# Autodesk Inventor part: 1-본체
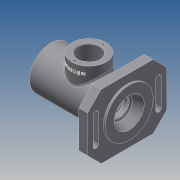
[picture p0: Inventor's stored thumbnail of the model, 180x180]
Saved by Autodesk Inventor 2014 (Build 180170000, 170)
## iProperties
Created: 2017-10
Part Number: 1-본체
Material: Generic
Document SubType Name: Modeling
Designer: kb543-11
Density: 1 g/cm^3
Appearance: Default
Author: kb543-11
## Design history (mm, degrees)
sketch "스케치1"
  geometry: L1 (-48.5, 0)-(-48.5, 24); L2 (-48.5, 24)-(-45.5, 24); L3 (-45.5, 24)-(-45.5, 20); L4 (-45.5, 20)-(-36.5, 20); L5 (-36.5, 20)-(-36.5, 17.5); L6 (-36.5, 17.5)-(-33.25, 17.5); L7 (-33.25, 17.5)-(-33.25, 18.5); L8 (-33.25, 18.5)-(-31.5, 18.5); L9 (-31.5, 18.5)-(-31.5, 17.5); L10 (-31.5, 17.5)-(-20.5, 17.5); L11 (-20.5, 17.5)-(-20.5, 26); L12 (-20.5, 26)-(17.5, 26); L13 (17.5, 26)-(17.5, 17.5); L14 (33.5, 16.5)-(33.5, 10); L15 (33.5, 10)-(36.2, 10); L16 (36.2, 10)-(36.2, 12.5); L17 (36.2, 12.5)-(42.8, 12.5); L18 (43.5, 16)-(57.5, 22); L19 (57.5, 22)-(57.5, 35); L20 (57.5, 0)-(-57.5, 0); L21 (43.5, 16)-(43.5, 12.904); L22 (42.8, 12.5)-(43.5, 12.904); L23 (17.5, 17.5)-(28.5, 17.5); L24 (28.5, 17.5)-(28.5, 16.5); L25 (28.5, 16.5)-(33.5, 16.5); L26 (-57.5, 31)-(-57.5, 0); L27 (57.5, 35)-(54.5, 35); L28 (-57.5, 31)-(54.5, 31); L29 (54.5, 31)-(54.5, 35); 2 further points
  constraints: 58 end point, 11 parallel, 5 perpendicular, 1 coincident, 1 midpoint, 1 point on line, 1 vertical, 1 vertical alignment
  dimensions: "d1" = 48 diameter of L2 L20; "d4" = 3 distance of L1.end L2.end; "d7" = 40 diameter of L4 L20; "d8" = 35 diameter of L6 L20; "d9" = 1.75 distance of L7.end L8.end; "d10" = 37 diameter of L8 L20; "d12" = 11 distance of L9.end L10.end; "d13" = 35 diameter of L10 L20; "d14" = 52 diameter of L12 L20; "d15" = 32 diameter of L18.start L20; "d16" = 44 diameter of L18.end L20; "d18" = 38 distance between parallel lines of L13 L11; "d19" = 14 distance between parallel lines of L19 L21; "d24" = 30 deg angle of L22 L17; "d25" = 0.7 horizontal distance of L21.end L17.end; "d26" = 7.3 distance between parallel lines of L16 L21; "d28" = 25 diameter of L17 L20; "d29" = 2.7 distance of L14.end L15.end; "d30" = 20 diameter of L15 L20; "d31" = 35 diameter of L23 L20; "d32" = 33 diameter of L25 L20; "d33" = 11 distance between parallel lines of L24 L13; "d90" = 12 distance between parallel lines of L3 L26; "d91" = 115 distance between parallel lines of L19 L26; "d92" = 21 distance between parallel lines of L26 L5; "d93" = 26 distance between parallel lines of L26 L9; "d101" = 62 diameter of L28 L20; "d102" = 3 distance of L19.end L27.end; "d103" = 70 diameter of L27 L20
revolve "회전1" sketch "스케치1" stored, may be unused: angle "d34" = 90 deg
sketch "스케치8"
  geometry: C1 r 31 at (0, 0) reference; 1 further point
  constraints: 1 coincident
hole "구멍2" sketch "스케치8" at (0, 0) diameter "d94" = 40.376; stored, may be unused: countersink angle "d98" = 90 deg, drill point angle "d100" = 118 deg; dims "d95" = 6, "d96" = 4, "d97" = 2, "d99" = 8
node "작업 평면1"
sketch "스케치2"
  geometry: L1 (-38, 47)-(38, 47); L2 (58, 27)-(58, -27); L3 (38, -47)-(-38, -47); L4 (-58, -27)-(-58, 27); L5 (-58, 47)-(58, -47); L6 (58, 47)-(-58, -47); L7 (-38, 47)-(-58, 27); L8 (-58, -27)-(-38, -47); L9 (38, -47)-(58, -27); L10 (58, 27)-(38, 47); C1 r 31 at (0, 0) reference; 1 further point
  constraints: 20 end point, 8 point on line, 2 midpoint, 2 parallel, 1 horizontal, 1 perpendicular
  dimensions: "d39" = 116 distance of L5.start L6.start; "d40" = 94 distance of L6.start L5.end; "d41" = 20 distance of L1.start L5.start; "d42" = 20 distance of L4.end L5.start (= d41); "d43" = 20 distance of L4.start L6.end (= d41); "d44" = 20 distance of L3.end L6.end (= d43); "d45" = 20 distance of L3.start L5.end (= d41); "d46" = 20 distance of L2.end L5.end (= d45); "d47" = 20 distance of L2.start L6.start; "d48" = 20 distance of L1.end L6.start (= d47)
extrude "돌출5" join sketch "스케치2" distance "d104" = 13; taper "d105" = 0 deg
sketch "스케치9"
  geometry: L1 (58, -27)-(58, 27) reference; L2 (46, -20)-(46, 20); L3 (42, -20)-(42, 20); L4 (50, 20)-(50, -20); L5 (-46, -20)-(-46, 20); L6 (-50, -20)-(-50, 20); L7 (-42, 20)-(-42, -20); C1 r 31 at (0, 0) reference; A1 r 4 centre (46, -20) between (42, -20) and (50, -20); A2 r 4 centre (46, 20) between (50, 20) and (42, 20); A3 r 4 centre (-46, -20) between (-50, -20) and (-42, -20); A4 r 4 centre (-46, 20) between (-42, 20) and (-50, 20); 2 further points
  constraints: 16 end point, 8 point on circle, 8 tangent, 4 centre point, 4 parallel, 3 horizontal alignment, 2 midpoint
  dimensions: "d106" = 46 distance from line of L2 C1.centre; "d107" = 92 distance between parallel lines of L5 L2; "d108" = 4 radius of A3; "d109" = 4 radius of A1; "d110" = 40 distance of L5.start L5.end
extrude "돌출6" cut sketch "스케치9" stored distance "d111" = 13; taper "d112" = 0 deg
node "작업 평면2"
sketch "스케치4"
  geometry: L1 (57.5, 31)-(57.5, -31) reference; C1 r 25 at (1.5, 0); 2 further points
  constraints: 1 centre point, 1 horizontal alignment, 1 midpoint
  dimensions: "d58" = 50 diameter of C1; "d59" = 56 distance from line of L1 C1.centre
extrude "돌출3" join sketch "스케치4" stored distance "d60" = 13; taper "d61" = 0 deg
sketch "스케치5"
  geometry: C1 r 25 at (0, 0) reference; C2 r 16 at (0, 0); 1 further point
  constraints: 1 centre point, 1 coincident
  dimensions: "d62" = 32 diameter of C2
extrude "돌출4" cut sketch "스케치5" stored distance "d63" = 13; taper "d64" = 0 deg
node "작업 평면3"
sketch "스케치6"
  geometry: L1 (-56, -78)-(-56, -16) reference; L2 (-25, 0)-(25, 0) reference; 2 further points
  constraints: 1 other
  dimensions: "d65" = 56 distance from line of L1 point (0, -10); "d66" = 10 distance from line of point (0, -10) L2
feature "엠보싱1" sketch "스케치6" dims "d1" = 48, "d4" = 3, "d7" = 40, "d8" = 35, "d9" = 1.75, "d10" = 37, "d12" = 11, "d13" = 35, "d14" = 52, "d15" = 32, "d16" = 44, "d18" = 38, "d19" = 14, "d24" = 30 deg, "d25" = 0.7, "d26" = 7.3, "d28" = 25, "d29" = 2.7, "d30" = 20, "d31" = 35, "d32" = 33, "d33" = 11, "d67" = 0.5, "d68" = 0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
sketch "스케치7"
  geometry: C1 r 16 at (0, 0) reference; 3 further points
  constraints: 2 vertical alignment
  dimensions: "d69" = 20.5 distance of C1.centre point (0, 20.5); "d70" = 41 distance of point (0, -20.5) point (0, 20.5)
hole "구멍1" sketch "스케치7" at (0, 20.5), (0, -20.5) diameter "d71" = 2.459; stored, may be unused: countersink angle "d75" = 90 deg, drill point angle "d77" = 118 deg; dims "d72" = 6, "d73" = 4, "d74" = 2, "d76" = 8
fillet "모깎기2" dims "d79" = 3
fillet "모깎기3" dims "d80" = 0.3
fillet "모깎기4" dims "d81" = 0.3
fillet "모깎기5" dims "d82" = 3
chamfer "모따기1" distance "d84" = 1; stored, may be unused: second distance "d85" = 2, angle "d86" = 45 deg
chamfer "모따기2" distance "d87" = 1; stored, may be unused: second distance "d88" = 2, angle "d89" = 45 deg
fillet "모깎기7" dims "d113" = 3
node "솔리드1"
other parameters: "d38" = -3, "d57" = 47
